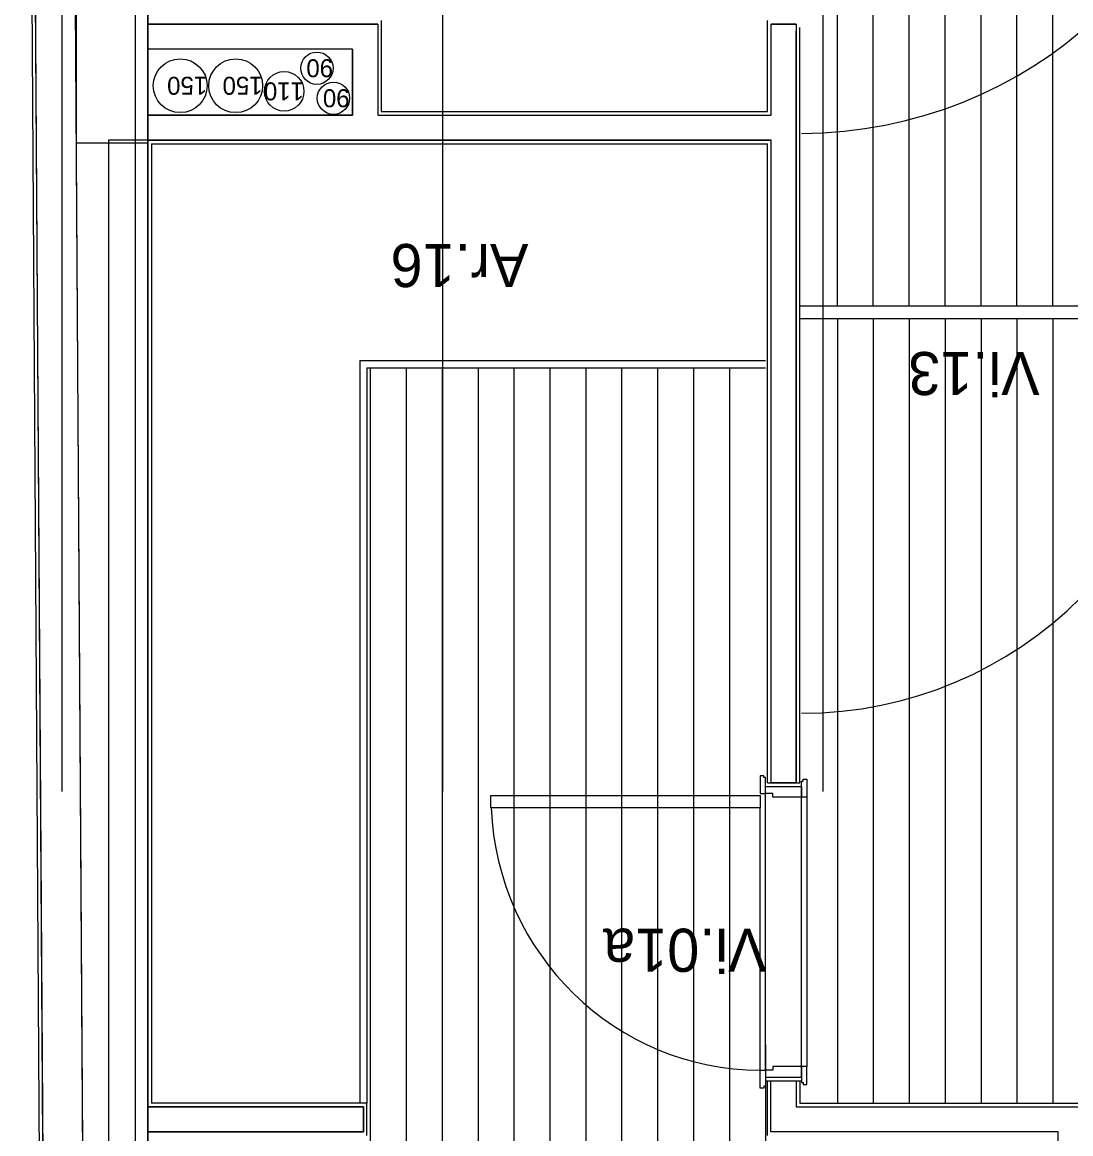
# Model space of a CAD drawing. Extents: x 1248 to 1356, y -443 to -224.
# Drawn here: x 1285.683 to 1288.603, y -235.881 to -232.785 of the extents above; entities that cross this region are included whole.
import ezdxf

# ---------------------------------------------------------------- set-up
doc = ezdxf.new("R2010")
doc.units = 0
for name, color, linetype in [('corte', 7, 'Continuous'), ('estereoctomias', 7, 'Continuous'), ('Level 1', 7, 'Continuous'), ('Level 10', 7, 'Continuous'), ('Level 13', 7, 'Continuous'), ('Level 4', 7, 'Continuous'), ('Level 40', 7, 'Continuous'), ('Level 41', 7, 'Continuous'), ('revestimentos', 7, 'Continuous'), ('vermelhos-cont', 7, 'Continuous'), ('vermelhos-tracej', 7, 'Continuous')]:
    doc.layers.add(name, color=color, linetype=linetype)

msp = doc.modelspace()

# ---------------------------------------------------------------- linework, layer by layer
at = {"layer": 'corte'}
for p, q in [((1285.7632, -239.414), (1285.6933, -228.434)), ((1286.6733, -232.7903), (1286.0333, -232.7903)), ((1286.6733, -232.7903), (1286.6733, -233.044)), ((1287.8386, -232.7903), (1287.7686, -232.7903)), ((1286.6033, -232.8603), (1286.0333, -232.8603)), ((1286.6033, -232.8603), (1286.6033, -233.044)), ((1286.6033, -233.044), (1286.0333, -233.044))]:
    msp.add_line(p, q, dxfattribs=at)
msp.add_lwpolyline([(1285.8333, -233.1214), (1286.0333, -233.1214), (1286.0333, -232.2214), (1285.8333, -232.2214)], close=True, dxfattribs=at)
at = {"layer": 'estereoctomias'}
for points in [[(1286.8442, -239.084), (1286.8442, -239.414), (1285.7632, -239.414), (1285.6933, -228.434), (1286.8442, -228.434), (1286.8442, -228.764), (1286.5833, -228.764), (1286.5833, -228.614), (1286.7742, -228.614), (1286.7742, -228.544), (1285.804, -228.544), (1285.8666, -238.3713), (1285.8333, -238.3713), (1285.8333, -239.2713), (1285.8723, -239.2713), (1285.8725, -239.304), (1286.7742, -239.304), (1286.7742, -239.234), (1286.0333, -239.234), (1286.0333, -239.084)], [(1287.8386, -234.904), (1287.7686, -234.904), (1287.7686, -233.114), (1286.0333, -233.114), (1286.0333, -233.044), (1286.6033, -233.044), (1286.6033, -232.8603), (1286.0333, -232.8603), (1286.0333, -232.7903), (1286.6733, -232.7903), (1286.6733, -233.044), (1287.7686, -233.044), (1287.7686, -232.7903), (1287.8386, -232.7903)], [(1286.0333, -233.114), (1285.9233, -233.114), (1285.9233, -238.3713), (1286.0333, -238.3713)], [(1288.6383, -239.084), (1288.5683, -239.084), (1288.5683, -235.8765), (1287.7685, -235.8765), (1287.7685, -235.734), (1287.8385, -235.734), (1287.8385, -235.8065), (1288.9685, -235.8065), (1288.9685, -235.734), (1289.0385, -235.734), (1289.0385, -235.8765), (1288.6383, -235.8765)], [(1286.6333, -235.8765), (1286.0333, -235.8765), (1286.0333, -235.8065), (1286.6333, -235.8065)]]:
    msp.add_lwpolyline(points, close=True, dxfattribs=at)
at = {"layer": 'Level 1'}
for p, q in [((1285.804, -228.544), (1285.8725, -239.304)), ((1286.0333, -228.764), (1286.0333, -233.114)), ((1287.7686, -233.044), (1287.7686, -232.7903)), ((1287.8386, -234.904), (1287.8386, -232.8103)), ((1286.6733, -233.044), (1287.7686, -233.044)), ((1285.9233, -233.1214), (1285.9233, -239.084)), ((1286.0333, -233.114), (1286.0333, -235.8065)), ((1286.0333, -233.114), (1287.7686, -233.114)), ((1287.7686, -234.904), (1287.7686, -233.114)), ((1287.7585, -234.904), (1287.8485, -234.904)), ((1287.7535, -235.734), (1287.8535, -235.734)), ((1287.7685, -235.8765), (1287.7685, -235.734)), ((1287.8385, -235.734), (1287.8385, -235.8065)), ((1286.0333, -235.8065), (1286.0333, -239.084)), ((1286.6333, -235.8065), (1286.0333, -235.8065)), ((1286.6333, -235.8765), (1286.6333, -235.8065)), ((1287.8385, -235.8065), (1288.9685, -235.8065)), ((1286.0333, -235.8765), (1286.6333, -235.8765)), ((1288.5683, -235.8765), (1287.7685, -235.8765)), ((1288.5683, -239.084), (1288.5683, -235.8765))]:
    msp.add_line(p, q, dxfattribs=at)
at = {"layer": 'Level 10'}
for p, q in [((1287.9535, -233.5753), (1287.9535, -232.0103)), ((1288.0535, -233.5753), (1288.0535, -232.0103)), ((1288.1535, -233.5753), (1288.1535, -232.0103)), ((1288.2535, -233.5753), (1288.2535, -232.0103)), ((1288.3535, -233.5753), (1288.3535, -232.0103)), ((1288.4535, -233.5753), (1288.4535, -232.0103)), ((1288.5535, -233.5753), (1288.5535, -232.0103)), ((1287.9535, -233.6103), (1287.9535, -235.7965)), ((1288.0535, -233.6103), (1288.0535, -235.7965)), ((1288.1535, -233.6103), (1288.1535, -235.7965)), ((1288.2535, -233.6103), (1288.2535, -235.7965)), ((1288.3535, -233.6103), (1288.3535, -235.7965)), ((1288.4535, -233.6103), (1288.4535, -235.7965)), ((1288.5535, -233.6103), (1288.5535, -235.7965)), ((1286.6535, -239.074), (1286.6535, -233.7476)), ((1286.7535, -239.074), (1286.7535, -233.7476)), ((1286.8535, -239.074), (1286.8535, -233.7476)), ((1286.9535, -239.074), (1286.9535, -233.7476)), ((1287.0535, -234.939), (1287.0535, -233.7476)), ((1287.1535, -234.939), (1287.1535, -233.7476)), ((1287.2535, -234.939), (1287.2535, -233.7476)), ((1287.3535, -234.939), (1287.3535, -233.7476)), ((1287.4535, -234.939), (1287.4535, -233.7476)), ((1287.5535, -234.939), (1287.5535, -233.7476)), ((1287.6535, -234.939), (1287.6535, -233.7476)), ((1287.0535, -239.074), (1287.0535, -234.874)), ((1287.1535, -239.074), (1287.1535, -234.874)), ((1287.2535, -239.074), (1287.2535, -234.874)), ((1287.3535, -239.074), (1287.3535, -234.874)), ((1287.4535, -239.074), (1287.4535, -234.874)), ((1287.5535, -239.074), (1287.5535, -234.874)), ((1287.6535, -239.074), (1287.6535, -234.874)), ((1287.7535, -235.704), (1287.7535, -234.934)), ((1287.8535, -235.694), (1287.8535, -234.944)), ((1287.7535, -235.634), (1287.7535, -239.074))]:
    msp.add_line(p, q, dxfattribs=at)
at = {"layer": 'Level 13'}
for p, q in [((1287.8486, -233.5753), (1288.9535, -233.5753)), ((1287.8486, -233.6103), (1288.9535, -233.6103)), ((1286.6233, -233.7276), (1286.6233, -235.7965)), ((1286.6233, -233.7276), (1287.7536, -233.7276)), ((1286.6433, -233.7476), (1286.6433, -235.7965)), ((1286.6433, -233.7476), (1287.7536, -233.7476)), ((1287.7385, -234.884), (1287.7385, -234.934)), ((1287.7485, -234.884), (1287.7385, -234.884)), ((1287.7485, -234.889), (1287.7485, -234.884)), ((1287.7535, -234.889), (1287.7485, -234.889)), ((1287.7535, -234.934), (1287.7535, -234.889)), ((1287.8535, -234.944), (1287.8535, -234.899)), ((1287.8535, -234.899), (1287.8585, -234.899)), ((1287.8585, -234.899), (1287.8585, -234.894)), ((1287.8585, -234.894), (1287.8685, -234.894)), ((1287.8685, -234.894), (1287.8685, -234.944)), ((1287.7385, -234.934), (1287.7535, -234.934)), ((1287.7535, -234.914), (1287.8535, -234.914)), ((1287.7535, -234.934), (1287.7535, -234.914)), ((1287.7735, -234.934), (1287.7535, -234.934)), ((1287.7735, -234.944), (1287.7735, -234.934)), ((1287.8535, -234.914), (1287.8535, -234.944)), ((1286.9885, -234.939), (1287.7385, -234.939)), ((1286.9885, -234.974), (1286.9885, -234.939)), ((1287.7385, -234.939), (1287.7385, -234.974)), ((1287.8535, -234.944), (1287.7735, -234.944)), ((1287.8685, -234.944), (1287.8535, -234.944)), ((1287.7385, -234.974), (1286.9885, -234.974)), ((1287.7385, -235.754), (1287.7385, -235.704)), ((1287.7385, -235.704), (1287.7535, -235.704)), ((1287.7735, -235.704), (1287.7535, -235.704)), ((1287.7535, -235.704), (1287.7535, -235.724)), ((1287.7535, -235.704), (1287.7535, -235.749)), ((1287.8535, -235.694), (1287.7735, -235.694)), ((1287.7735, -235.694), (1287.7735, -235.704)), ((1287.8535, -235.724), (1287.8535, -235.694)), ((1287.8685, -235.694), (1287.8535, -235.694)), ((1287.8535, -235.694), (1287.8535, -235.739)), ((1287.8685, -235.744), (1287.8685, -235.694)), ((1287.7535, -235.724), (1287.8535, -235.724)), ((1287.8535, -235.739), (1287.8585, -235.739)), ((1287.8585, -235.739), (1287.8585, -235.744)), ((1287.7485, -235.754), (1287.7385, -235.754)), ((1287.7535, -235.749), (1287.7485, -235.749)), ((1287.7485, -235.749), (1287.7485, -235.754)), ((1287.8585, -235.744), (1287.8685, -235.744))]:
    msp.add_line(p, q, dxfattribs=at)
at = {"layer": 'Level 4'}
for p, q in [((1287.8685, -234.944), (1287.8685, -235.694)), ((1287.7385, -235.704), (1287.7385, -234.974))]:
    msp.add_line(p, q, dxfattribs=at)
msp.add_arc((1287.8535, -233.6103), 1.1, 270, 0, dxfattribs=at)
for centre, major_axis, ratio, start_param, end_param in [((1287.8442, -232.0103), (-1.165, 0), 0.93133, 1.578735, 3.141609), ((1287.7385, -234.9408), (0, 0.7632), 0.982661, 1.614288, 3.141593)]:
    msp.add_ellipse(centre, major_axis=major_axis, ratio=ratio, start_param=start_param, end_param=end_param, dxfattribs=at)
at = {"layer": 'Level 41'}
for centre, radius in [((1286.1233, -232.9622), 0.075), ((1286.2777, -232.9622), 0.075), ((1286.5039, -232.9133), 0.045), ((1286.4129, -232.9778), 0.055), ((1286.55, -232.997), 0.045)]:
    msp.add_circle(centre, radius, dxfattribs=at)
at = {"layer": 'revestimentos'}
for p, q in [((1285.7533, -239.424), (1285.6833, -228.424)), ((1286.6833, -232.7803), (1286.6833, -233.034)), ((1287.7586, -233.034), (1287.7586, -232.7803)), ((1287.8486, -234.904), (1287.8486, -232.8003)), ((1286.6833, -233.034), (1287.7586, -233.034)), ((1286.0433, -233.124), (1287.7586, -233.124)), ((1286.0433, -233.124), (1286.0433, -235.7965)), ((1287.7586, -234.904), (1287.7586, -233.124)), ((1287.7585, -235.8865), (1287.7585, -235.734)), ((1287.8485, -235.734), (1287.8485, -235.7965)), ((1286.6433, -235.7965), (1286.0433, -235.7965)), ((1286.6433, -235.8865), (1286.6433, -235.7965)), ((1287.8485, -235.7965), (1288.9585, -235.7965))]:
    msp.add_line(p, q, dxfattribs=at)
at = {"layer": 'vermelhos-cont'}
msp.add_line((1285.9976, -225.5674), (1285.9976, -250.7923), dxfattribs=at)
at = {"layer": 'vermelhos-tracej'}
for p, q in [((1285.7942, -234.928), (1285.7942, -224.3117)), ((1286.8542, -234.928), (1286.8542, -224.3117)), ((1287.9141, -234.928), (1287.9141, -224.3117))]:
    msp.add_line(p, q, dxfattribs=at)

# ---------------------------------------------------------------- texts
at = {"layer": 'Level 40'}
for s, p in [('Ar.16', (1287.0929, -233.403)), ('Vi.13', (1288.5167, -233.7038)), ('Vi.01a', (1287.756, -235.3103))]:
    msp.add_text(s, height=0.12, rotation=180, dxfattribs=at).set_placement(p)
at = {"layer": 'Level 41'}
for s, p in [('90', (1286.5489, -232.8883)), ('150', (1286.1983, -232.9372)), ('150', (1286.3527, -232.9372)), ('110', (1286.4679, -232.9528)), ('90', (1286.595, -232.972))]:
    msp.add_text(s, height=0.05, rotation=180, dxfattribs=at).set_placement(p)

doc.saveas('drawing.dxf')
